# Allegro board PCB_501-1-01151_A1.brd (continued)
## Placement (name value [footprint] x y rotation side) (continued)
R204  10K  [0402]  93.85 53.34 90 top
R205  470E  [0402]  98.04 43.31 90 top
R206  470E  [0402]  96.9 43.31 90 top
R207  470E  [0402]  97.66 37.97 90 top
R208  10K  [0402]  94.49 60.32 90 top
R209  10K  [0402]  46.74 22.99 90 top
R210  10K  [0402]  49.02 22.99 90 top
R211  10K  [0402]  47.88 22.99 90 top
R212  10K  [0402]  43.31 22.99 90 top
R213  10K  [0402]  44.45 22.99 90 top
R214  10K  [0402]  51.31 22.99 90 top
R215  10K  [0402]  50.16 22.99 90 top
R216  10K  [0402]  45.59 22.99 90 top
R217  10K  [0402]  78.1 14.22 270 top
R218  10K  [0402]  77.34 10.41 90 top
R219  10K  [0402]  76.58 14.22 270 top
R220  10K  [0402]  75.82 10.41 90 top
R221  10K  [0402]  75.06 14.22 270 top
R222  10K  [0402]  74.29 10.41 90 top
R223  10K  [0402]  73.41 14.22 270 top
R224  10K  [0402]  72.64 10.41 90 top
R225  1K  [0402]  77.34 16 270 bottom
R226  1K  [0402]  78.49 16 270 bottom
R227  1K  [0402]  79.63 16 270 bottom
R228  1K  [0402]  69.34 10.41 270 top
R229  10K  [0402]  68.58 14.22 270 top
R230  10K  [0402]  69.34 8.76 270 top
R231  10K  [0402]  67.69 8.89 90 top
R232  1K  [0402]  80.77 16 270 bottom
R236  10K  [0402]  61.6 9.78 270 bottom
R238  10K  [0402]  62.48 11.3 270 bottom
R239  10K  [0402]  63.25 9.78 270 bottom
R240  10K  [0402]  68.71 14.22 270 bottom
R241  10K  [0402]  69.6 12.83 270 bottom
R242  10K  [0402]  70.41 14.25 270 bottom
R243  10K  [0402]  71.12 12.7 270 bottom
R244  10K  [0402]  71.88 14.22 270 bottom
R245  10K  [0402]  72.64 12.7 270 bottom
R246  10K  [0402]  73.41 14.22 270 bottom
R247  10K  [0402]  74.29 12.7 270 bottom
R248  10K  [0402]  75.06 14.22 270 bottom
R249  10K  [0402]  75.82 12.7 270 bottom
R250  10K  [0402]  76.58 14.22 270 bottom
R251  10K  [0402]  77.34 12.7 270 bottom
R252  10K  [0402]  78.1 14.22 270 bottom
R253  10K  [0402]  45.59 25.15 270 top
R254  10K  [0402]  50.16 25.15 270 top
R255  10K  [0402]  51.31 25.15 270 top
R256  10K  [0402]  44.45 25.15 270 top
R257  10K  [0402]  43.31 25.15 270 top
R258  10K  [0402]  47.88 25.15 270 top
R259  10K  [0402]  49.02 25.15 270 top
R260  10K  [0402]  46.74 25.15 270 top
R261  0E  [0402]  81.91 7.37 180 top
R262  100K  [0402]  83.69 5.97 180 top
R263  510K  [0402]  52.58 50.42 0 top
R264  0E  [0402]  2.79 49.02 0 top
R265  10K  [0402]  12.45 72.01 0 top
R266  10K  [0402]  12.45 69.47 0 top
R267  10K  [0402]  12.45 59.31 0 top
R387  10K  [0402]  33.91 40.51 180 bottom
R569  4.7K  [0402]  33.91 39.37 0 bottom
R571  2.2K  [0402]  50.16 11.68 90 bottom
R572  2.2K  [0402]  51.31 11.68 270 bottom
R574  2.2K  [0402]  52.07 29.46 90 bottom
R575  10K  [0402]  95.12 30.35 180 bottom
R576  10K  [0402]  95.12 31.5 180 bottom
R577  12K  [0402]  76.59 73.59 270 top
R578  10K  [0402]  93.6 80.39 180 top
R579  10K  [0402]  93.6 81.53 0 top
R580  10K  [0402]  18.29 68.2 90 top
R581  10K  [0402]  17.02 54.1 90 top
R763  200K  [0402]  37.97 64.13 90 bottom
R765  10K  [0402]  34.67 60.45 90 bottom
R766  1K  [0402]  42.67 63.5 90 bottom
R768  0E  [0402]  44.45 66.04 270 bottom
R769  0E  [0402]  52.07 60.71 180 top
R770  10K  [0402]  44.7 39.24 0 top
R771  0E  [0402]  91.69 86.87 90 top
R772  100K  [0402]  30.1 40.89 90 bottom
R773  49.9E  [0402]  51.69 37.59 90 bottom
R779  49.9E  [0402]  51.69 39.37 270 bottom
R780  10mE  [0603]  53.59 57.53 180 top
R781  1K  [0402]  22.48 55.24 90 top
R782  1K  [0402]  23.62 55.24 270 top
R783  2.2K  [0402]  53.59 11.68 270 bottom
R784  2.2K  [0402]  53.85 25.91 90 bottom
R785  2.2K  [0402]  48.9 17.27 90 top
R790  49.9E  [0402]  33.78 19.18 90 bottom
R791  49.9E  [0402]  33.78 17.27 90 bottom
R792  49.9E  [0402]  33.78 15.24 90 bottom
R793  49.9E  [0402]  33.78 13.34 90 bottom
R794  49.9E  [0402]  33.53 24.13 270 bottom
R795  49.9E  [0402]  33.53 26.03 270 bottom
R796  49.9E  [0402]  33.53 27.81 270 bottom
R797  49.9E  [0402]  33.53 29.72 270 bottom
R798  2.2K  [0402]  45.34 10.8 180 bottom
R799  2.2K  [0402]  45.85 30.99 180 bottom
R800  0E  [0402]  33.27 87.76 180 bottom
R801  0E  [0402]  33.27 89.03 180 bottom
R802  0E  [0402]  37.59 67.69 0 top
R803  0E  [0402]  58.17 58.29 90 top
R805  100K  [0402]  30.86 38.48 270 top
R806  100K  [0402]  29.84 85.6 180 bottom
R807  10K  [0402]  79.86 13.64 180 bottom
R808  10K  [0402]  79.88 12.45 0 bottom
R809  33E  [0402]  72.64 33.15 0 bottom
R810  0E  [0402]  36.2 17.02 0 top
R811  0E  [0402]  36.17 15.43 0 top
R812  0E  [0402]  35.92 25.43 0 top
R813  0E  [0402]  35.81 27.88 0 top
R814  10K  [0402]  36.2 39.37 0 bottom
R815  10K  [0402]  36.2 40.51 0 bottom
R816  10K  [0402]  63.75 62.74 0 top
R817  10K  [0402]  61.72 66.42 90 top
R818  10K  [0402]  61.98 70.49 180 top
R819  10K  [0402]  61.85 72.77 180 top
R820  10K  [0402]  68.33 62.74 270 top
R821  2.2M  [0402]  55.12 54.23 90 top
R822  22E  [0402]  68.07 21.72 0 top
R823  22E  [0402]  68.07 24 0 top
R824  22E  [0402]  68.07 25.15 0 top
R825  22E  [0402]  68.07 19.43 0 top
R826  22E  [0402]  68.07 20.57 0 top
R827  22E  [0402]  68.07 22.86 0 top
R828  22E  [0402]  68.07 26.29 0 top
R829  22E  [0402]  68.07 27.43 0 top
R830  22E  [0402]  68.07 17.14 0 top
R831  0E  [0402]  7.49 42.29 90 bottom
R832  10K  [0402]  47.37 43.56 0 bottom
R833  0E  [0402]  91.57 82.8 180 top
R834  0E  [0402]  11.3 49.02 0 top
R835  0E  [0402]  11.3 47.75 0 top
R836  100K  [0402]  31.24 37.97 180 bottom
R839  100K  [0402]  31.24 36.83 0 bottom
R840  100K  [0402]  31.24 39.12 0 bottom
R841  0E  [0402]  14.86 52.7 90 top
R842  0E  [0402]  93.98 68.58 0 top
R843  200K  [0402]  93.98 69.85 0 top
R844  2.2K  [0402]  39.37 11.3 90 bottom
R845  2.2K  [0402]  38.1 11.3 270 bottom
R846  2.2K  [0402]  40.13 32.89 270 bottom
R847  2.2K  [0402]  38.99 32.89 90 bottom
R848  10K  [0402]  12.45 74.55 180 top
R851  10K  [0402]  12.45 64.39 180 top
R852  10K  [0402]  12.45 61.85 180 top
R854  10K  [0402]  12.45 56.77 0 top
R855  10K  [0402]  12.45 52.96 0 top
R856  0E  [0402]  12.45 54.23 0 top
R857  0E  [0402]  12.45 51.69 0 top
R858  47K  [0402]  66.29 27.43 0 top
R859  0E  [0402]  53.34 65.91 270 top
R860  0E  [0402]  52.2 65.91 270 top
R861  0E  [0402]  41.66 11.3 270 bottom
R862  0E  [0402]  45.21 33.53 0 top
R863  2.2K  [0402]  40.51 11.3 90 bottom
R864  2.2K  [0402]  41.27 32.89 270 bottom
R865  0E  [0402]  33.27 90.17 180 bottom
R866  100K  [0402]  62.23 55.24 270 bottom
R867  100K  [0402]  11.68 46.23 0 top
R868  100K  [0402]  11.81 43.94 0 top
R869  100K  [0402]  23.75 46.1 270 top
R870  100K  [0402]  73.41 56.77 180 top
R871  100K  [0402]  65.28 53.98 270 bottom
R872  0E  [0402]  94.23 54.74 0 top
R873  0E  [0402]  94.87 62.1 0 top
R874  100K  [0402]  96.14 85.72 270 top
R875  0E  [0402]  17.02 68.2 270 top
R876  0E  [0402]  17.02 55.75 270 top
SW1  OS102011MS2QN1  [SW3_2_8P6X4P3_TH_ST]  15.49 96.27 0 top
SW2  B3U-3100PM-B  [SW3_1P7_3X2P5_SM_RA_A1]  98.75 69.72 270 top
SW3  B3U-3100PM-B  [SW3_1P7_3X2P5_SM_RA_A1]  98.75 75.69 270 top
SW4  B3U-3100PM-B  [SW3_1P7_3X2P5_SM_RA_A1]  98.75 53.09 270 top
SW5  B3U-3100PM-B  [SW3_1P7_3X2P5_SM_RA_A1]  98.75 59.31 270 top
SW6  TDA04H0SB1  [SW04_1P27_6P21X6P2]  71.37 20.19 0 bottom
SW7  TDA02H0SB1  [SW4_1P27_3P67X6P2]  92.58 37.21 0 bottom
SW8  B3U-3100PM-B  [SW3_1P7_3X2P5_SM_RA_A1]  98.75 81.66 270 top
TP1  SMD  [TP40_SMD]  29.08 81.15 0 top
TP3  SMD  [TP35_SMD]  69.72 33.02 180 bottom
TP4  SMD  [TP35_SMD]  76.45 29.46 180 bottom
TP5  SMD  [TP40_SMD]  50.04 20.19 0 top
TP6  SMD  [TP40_SMD]  47.12 20.57 0 top
TP7  SMD  [TP40_SMD]  17.91 52.58 0 top
TP8  SMD  [TP40_SMD]  50.42 68.96 90 top
TP9  SMD  [TP40_SMD]  49.91 46.1 90 top
TP10  SMD  [TP40_SMD]  46.1 44.2 0 top
TP11  SMD  [TP40_SMD]  32 54.1 90 top
TP12  SMD  [TP40_SMD]  38.1 43.18 0 top
TP13  SMD  [TP40_SMD]  34.67 89.15 90 top
TP30  SMD  [TP40_SMD_A1]  86.76 73.19 0 top
TP31  SMD  [TP40_SMD_A1]  41.78 5.84 0 top
TP32  SMD  [TP40_SMD_A1]  42.16 76.2 0 top
TP33  SMD  [TP40_SMD]  54.1 49.91 0 top
TP34  SMD  [TP40_SMD]  96.77 78.61 0 top
TP35  SMD  [TP40_SMD]  15.11 67.82 0 top
TP36  SMD  [TP40_SMD]  36.7 69.98 0 top
TP37  SMD  [TP40_SMD]  45.85 71.75 0 top
TP38  SMD  [TP40_SMD]  54.48 56.13 0 top
TP39  SMD  [TP40_SMD]  35.18 60.32 0 top
TP40  SMD  [TP40_SMD]  56.77 64.01 0 top
TP41  SMD  [TP40_SMD_A1]  88 47.84 180 bottom
TP42  SMD  [TP40_SMD_A1]  42.89 73.37 180 bottom
TP43  SMD  [TP40_SMD_A1]  47 4.53 180 bottom
TP44  SMD  [TP40_SMD]  47.88 50.16 0 top
TP45  SMD  [TP40_SMD]  45.72 46.86 0 top
TP46  SMD  [TP40_SMD]  39.62 50.55 0 top
TP47  SMD  [TP40_SMD]  45.85 67.69 0 top
TP48  SMD  [TP40_SMD]  40.39 38.23 0 top
TP49  SMD  [TP40_SMD]  60.2 32.13 180 bottom
TP50  SMD  [TP40_SMD]  68.07 44.2 180 bottom
TP51  SMD  [TP40_SMD]  58.8 29.97 180 bottom
TP52  SMD  [TP40_SMD]  55.24 53.98 180 bottom
TP53  SMD  [TP40_SMD]  64.01 49.02 180 bottom
TP54  SMD  [TP40_SMD]  49.78 49.02 180 bottom
TP55  SMD  [TP_3P8X2P03_SMD_A1]  95.1 64.73 0 top
TP56  SMD  [TP_3P8X2P03_SMD_A1]  28.36 96.37 90 top
TP57  SMD  [TP_3P8X2P03_SMD_A1]  94.72 13.3 0 top
TP58  SMD  [TP40_SMD]  42.93 35.18 0 top
TP59  SMD  [TP40_SMD]  39.24 35.31 0 top
TP60  SMD  [TP40_SMD]  44.96 41.15 0 top
U1  TPS6521815RSL  [VQFN48_0P4_6X6_EP_A1]  44.07 58.93 180 top
U2  SN74LV1T126DCK  [SC70-5L_0P65_2X1P25_B_A1]  55.75 60.71 270 top
U3  TPS22964C  [BGA6_0P5_0P942X1P442_A1]  29.84 40.26 0 top
U4  FPF1321UCX  [WLCSP6_0P5_0P96X1P46_A1]  91.19 23.11 90 top
U5  TPS22964C  [BGA6_0P5_0P942X1P442_A1]  32.13 83.44 180 top
U6  MCIMX6Y2CVM08AB  [BGA289_0P8_14X14_A1]  60.2 41.78 180 top
U7  MT41K256M16TW-107:P  [BGA96_0P8_8X14_A1]  81.41 40.01 0 top
U8  MTFC8GAKAJCN-4M  [BGA153_0P5_11P5X13_C_A1]  77.22 24.64 90 top
U9  MT25QU256ABA1EW7  [WPDFN8_1P27_6X5_EP_A1]  72.26 29.08 0 bottom
U10  DP83849IDVS  [QFP80_0P5_12X12]  45.47 20.7 180 bottom
U11  PUSB3F96  [DFN2510A-10L_0P5_2P5X1]  30.61 16.26 270 bottom
U12  PUSB3F96  [DFN2510A-10L_0P5_2P5X1]  29.97 27.94 90 bottom
U13  AT24C02C-MAHM  [UDFN8_0P5_3X2_EP_A_A1]  83.44 61.47 90 bottom
U14  USB2517I  [QFN64_0P5_9X9_EP_Y_A1]  70.74 69.34 270 top
U15  PUSB3F96  [DFN2510A-10L_0P5_2P5X1]  79.5 79.12 270 top
U16  PUSB3F96  [DFN2510A-10L_0P5_2P5X1]  60.96 79.25 90 top
U17  PUSB3F96  [DFN2510A-10L_0P5_2P5X1]  5.46 29.84 0 top
U18  TPS2054BD  [SOIC16_1P27_3P9X9P9_A1]  90.42 62.87 90 bottom
U19  MIC2026-1YM  [SOIC8_1P27_4X5]  54.61 72.39 180 bottom
U20  FT230XS  [SSOP16_0P635_5X4]  14.86 45.09 180 bottom
U21  ECMF02-2  [BGA5_0P4_0P83X1P23_A1]  8.51 40.51 180 top
U22  INA3221AIRGV  [QFN16_0P65_4X4_EP_I_A1]  30.86 45.97 270 bottom
U23  INA3221AIRGV  [QFN16_0P65_4X4_EP_I_A1]  34.92 69.6 0 bottom
U24  TSC2046IPW  [TSSOP16_0P65_4P4X5_F_A1]  63.63 15.88 0 bottom
U26  TPS3422EGDRY  [SON6_0P5_1X1P45_A1]  91.69 80.9 270 top
U27  SN74LV1T126DCK  [SC70-5L_0P65_2X1P25_B_A1]  93.73 87.5 180 top
X1  24MHz  [XTAL4_1P55_3P2X2P5]  81.74 71.91 270 top
X2  32.768KHz  [XTAL2_2P5_3P2X1P5]  62.54 52 90 bottom
X3  24MHz  [XTAL4_1P6_3P2X2P5_A_A1]  52.2 53.85 0 top
Y1  50MHz  [OSC4_2P2_5P2X3P4]  55.74 17.18 90 bottom

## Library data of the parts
BH1 = BATT_HOLDER_3P_B
C1 C2 C4-C24 C26-C143 C149-C177 C180-C201 C204 C205 C572-C577 C583-C589 C591-C594 C596-C607 = CAP_NP
C3 C590 = CAP_POL
D1 = DIODE_ZEN
D2 D6 D9 D12 D26-D29 = DIODE_SCH
D4 D5 D7 D8 D10 D11 = DIODE_LED
D15 = DIODE_LED_A
DA1-DA6 = DIODE_NETX2_LED-GR_4P
DA8 = DIODE_NETX2_LED-BO_4P
F1 = FUSE
FB1 FB3-FB20 = FER_BEAD
FD1-FD6 = MECH_FID_G
FD7-FD12 = MECH_FID_L
FL1-FL6 = FIL_COM-MODE_4P_C_POL
H1 = HDR_2X5_10P
H4 H5 = HDR_2X10_20P
J1 = CONN_PWRJACK_4P_A_A1
J2 = CONN_MICROSD-8_12P_B
J3 = CONN_RJ45-17X2_39P_A_A1
J4 J5 = CONN_USBA-4X2_12P
J6 = CONN_USBA-4X1_8P
J7 = CONN_USB-5X1_9P
J8 = CONN_USB-5X1_11P
J9 = CONN_FPC-40_42P
L1-L4 = IND_CORE_A
L5-L7 = IND_CORE_B
MH1-MH8 = MECH_MH_PL
P1-P15 = PROT_ZENX2_NET_2P_A
Q1 = TRANS_PMOSX1_8P
Q2 = TRANS_PNP
Q3 = TRANS_NMOS-ENX1_3P
Q4-Q6 = TRANS_PMOS-ENX1_3P_C
Q17 Q41 = TRANS_NPN
R1 R3-R28 R31-R37 R58 R60 R62-R90 R94-R110 R112-R232 R236 R238-R267 R387 R569 R571 R572 R574-R581 R763 R765 R766 R768-R773 R779-R785 R790-R803 R805-R836 R839-R848 R851 R852 R854-R876 = RES
SW1 = SWITCH_SPDT_5P
SW2-SW5 SW8 = SWITCH_PUSH-2_3P_A
SW6 = SWITCH_DIPX4_8P_B
SW7 = SWITCH_DIPX2_4P_B
TP1 TP3-TP13 TP30-TP60 = TEST_POINT_SMD
U1 = IC_TPS65218D0_QFN-48P_EP_CST_A2
U2 U27 = IC_GATE_BUFX1_5P_H_A1
U3 U5 = IC_LOAD_SWITCH_6P_F_A1
U4 = IC_LOAD_SWITCH_6P_N_A1
U6 = IC_IMX6ULL_BGA-289P_CST_A1
U7 = IC_DDR3-SDRAMX16_BGA-96P_D
U8 = IC_NAND_FLASHx8_BGA-153P_J_A1
U9 = IC_NORFLASH-SPI_8P_EP_G_A1
U10 = IC_DP83849ID_TQFP-80P
U11 U12 U15-U17 = IC_PUSB3F96_DFN-10P
U13 = IC_EEPROM-I2C_8P_EP_B_A1
U14 = IC_USB2517_QFN-64P_EP_CUST_A1
U18 = IC_PWRSWITCHx4_16P_C_A1
U19 = IC_PWRSWITCH_8P_D_A1
U20 = IC_FT230X_SSOP-16P
U21 = IC_FIL_COM-MODE_WLCSP-5P
U22 U23 = IC_INA3221_VQFN-16P_EP_A1
U24 = IC_TSC2046_TSSOP-16P_A1
U26 = IC_TPS3422_USON-6P_A1
X1 = CRYSTAL_4P_D
X2 = CRYSTAL
X3 = CRYSTAL_4P
Y1 = OSC_4P_A

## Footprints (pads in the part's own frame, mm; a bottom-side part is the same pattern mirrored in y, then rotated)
0201
  rect 0.508x0.508 smd: 1(-0.354,0) 2(0.354,0)
0402
  rect 0.533x0.533 smd: 1(-0.4,0) 2(0.4,0)
0603
  rect 0.965x1.016 smd: 1(-0.8,0) 2(0.8,0)
0805
  rect 1.143x1.448 smd: 1(-0.9,0) 2(0.9,0)
0805_B_A1
  rect 0.711x1.321 smd: 1(-0.95,0) 2(0.95,0)
BAT3_21P97_21P08X15P24_A1
  rect 2.794x5.08 smd: 1(-10.985,0) 3(10.985,0)
  round 17.78 smd: 2(0,0)
BGA5_0P4_0P83X1P23_A1
  round 0.229 smd: A1(-0.2,0.4) A2(0.2,0.4) B1(-0.2,0) B2(0.2,0) C2(0.2,-0.4)
BGA6_0P5_0P942X1P442_A1
  round 0.229 smd: A1(-0.25,0.5) A2(0.25,0.5) B1(-0.25,0) B2(0.25,0) C1(-0.25,-0.5) C2(0.25,-0.5)
BGA96_0P8_8X14_A1
  round 0.356 smd: A1(-3.2,6) A2(-2.4,6) A3(-1.6,6) A7(1.6,6) A8(2.4,6) A9(3.2,6) B1(-3.2,5.2) B2(-2.4,5.2) B3(-1.6,5.2) B7(1.6,5.2) B8(2.4,5.2) B9(3.2,5.2) C1(-3.2,4.4) C2(-2.4,4.4) C3(-1.6,4.4) C7(1.6,4.4) C8(2.4,4.4) C9(3.2,4.4) D1(-3.2,3.6) D2(-2.4,3.6) D3(-1.6,3.6) D7(1.6,3.6) D8(2.4,3.6) D9(3.2,3.6) E1(-3.2,2.8) E2(-2.4,2.8) E3(-1.6,2.8) E7(1.6,2.8) E8(2.4,2.8) E9(3.2,2.8) F1(-3.2,2) F2(-2.4,2) F3(-1.6,2) F7(1.6,2) F8(2.4,2) F9(3.2,2) G1(-3.2,1.2) G2(-2.4,1.2) G3(-1.6,1.2) G7(1.6,1.2) G8(2.4,1.2) G9(3.2,1.2) H1(-3.2,0.4) H2(-2.4,0.4) H3(-1.6,0.4) H7(1.6,0.4) H8(2.4,0.4) H9(3.2,0.4) J1(-3.2,-0.4) J2(-2.4,-0.4) J3(-1.6,-0.4) J7(1.6,-0.4) J8(2.4,-0.4) J9(3.2,-0.4) K1(-3.2,-1.2) K2(-2.4,-1.2) K3(-1.6,-1.2) K7(1.6,-1.2) K8(2.4,-1.2) K9(3.2,-1.2) L1(-3.2,-2) L2(-2.4,-2) L3(-1.6,-2) L7(1.6,-2) L8(2.4,-2) L9(3.2,-2) M1(-3.2,-2.8) M2(-2.4,-2.8) M3(-1.6,-2.8) M7(1.6,-2.8) M8(2.4,-2.8) M9(3.2,-2.8) N1(-3.2,-3.6) N2(-2.4,-3.6) N3(-1.6,-3.6) N7(1.6,-3.6) N8(2.4,-3.6) N9(3.2,-3.6) P1(-3.2,-4.4) P2(-2.4,-4.4) P3(-1.6,-4.4) P7(1.6,-4.4) P8(2.4,-4.4) P9(3.2,-4.4) R1(-3.2,-5.2) R2(-2.4,-5.2) R3(-1.6,-5.2) R7(1.6,-5.2) R8(2.4,-5.2) R9(3.2,-5.2) T1(-3.2,-6) T2(-2.4,-6) T3(-1.6,-6) T7(1.6,-6) T8(2.4,-6) T9(3.2,-6)
BGA153_0P5_11P5X13_C_A1
  round 0.254 smd: A1(-3.25,3.25) A2(-2.75,3.25) A3(-2.25,3.25) A4(-1.75,3.25) A5(-1.25,3.25) A6(-0.75,3.25) A7(-0.25,3.25) A8(0.25,3.25) A9(0.75,3.25) A10(1.25,3.25) A11(1.75,3.25) A12(2.25,3.25) A13(2.75,3.25) A14(3.25,3.25) B1(-3.25,2.75) B2(-2.75,2.75) B3(-2.25,2.75) B4(-1.75,2.75) B5(-1.25,2.75) B6(-0.75,2.75) B7(-0.25,2.75) B8(0.25,2.75) B9(0.75,2.75) B10(1.25,2.75) B11(1.75,2.75) B12(2.25,2.75) B13(2.75,2.75) B14(3.25,2.75) C1(-3.25,2.25) C2(-2.75,2.25) C3(-2.25,2.25) C4(-1.75,2.25) C5(-1.25,2.25) C6(-0.75,2.25) C7(-0.25,2.25) C8(0.25,2.25) C9(0.75,2.25) C10(1.25,2.25) C11(1.75,2.25) C12(2.25,2.25) C13(2.75,2.25) C14(3.25,2.25) D1(-3.25,1.75) D2(-2.75,1.75) D3(-2.25,1.75) D4(-1.75,1.75) D12(2.25,1.75) D13(2.75,1.75) D14(3.25,1.75) E1(-3.25,1.25) E2(-2.75,1.25) E3(-2.25,1.25) E5(-1.25,1.25) E6(-0.75,1.25) E7(-0.25,1.25) E8(0.25,1.25) E9(0.75,1.25) E10(1.25,1.25) E12(2.25,1.25) E13(2.75,1.25) E14(3.25,1.25) F1(-3.25,0.75) F2(-2.75,0.75) F3(-2.25,0.75) F5(-1.25,0.75) F10(1.25,0.75) F12(2.25,0.75) F13(2.75,0.75) F14(3.25,0.75) G1(-3.25,0.25) G2(-2.75,0.25) G3(-2.25,0.25) G5(-1.25,0.25) G10(1.25,0.25) G12(2.25,0.25) G13(2.75,0.25) G14(3.25,0.25) H1(-3.25,-0.25) H2(-2.75,-0.25) H3(-2.25,-0.25) H5(-1.25,-0.25) H10(1.25,-0.25) H12(2.25,-0.25) H13(2.75,-0.25) H14(3.25,-0.25) J1(-3.25,-0.75) J2(-2.75,-0.75) J3(-2.25,-0.75) J5(-1.25,-0.75) J10(1.25,-0.75) J12(2.25,-0.75) J13(2.75,-0.75) J14(3.25,-0.75) K1(-3.25,-1.25) K2(-2.75,-1.25) K3(-2.25,-1.25) K5(-1.25,-1.25) K6(-0.75,-1.25) K7(-0.25,-1.25) K8(0.25,-1.25) K9(0.75,-1.25) K10(1.25,-1.25) K12(2.25,-1.25) K13(2.75,-1.25) K14(3.25,-1.25) L1(-3.25,-1.75) L2(-2.75,-1.75) L3(-2.25,-1.75) L12(2.25,-1.75) L13(2.75,-1.75) L14(3.25,-1.75) M1(-3.25,-2.25) M2(-2.75,-2.25) M3(-2.25,-2.25) M4(-1.75,-2.25) M5(-1.25,-2.25) M6(-0.75,-2.25) M7(-0.25,-2.25) M8(0.25,-2.25) M9(0.75,-2.25) M10(1.25,-2.25) M11(1.75,-2.25) M12(2.25,-2.25) M13(2.75,-2.25) M14(3.25,-2.25) N1(-3.25,-2.75) N2(-2.75,-2.75) N3(-2.25,-2.75) N4(-1.75,-2.75) N5(-1.25,-2.75) N6(-0.75,-2.75) N7(-0.25,-2.75) N8(0.25,-2.75) N9(0.75,-2.75) N10(1.25,-2.75) N11(1.75,-2.75) N12(2.25,-2.75) N13(2.75,-2.75) N14(3.25,-2.75) P1(-3.25,-3.25) P2(-2.75,-3.25) P3(-2.25,-3.25) P4(-1.75,-3.25) P5(-1.25,-3.25) P6(-0.75,-3.25) P7(-0.25,-3.25) P8(0.25,-3.25) P9(0.75,-3.25) P10(1.25,-3.25) P11(1.75,-3.25) P12(2.25,-3.25) P13(2.75,-3.25) P14(3.25,-3.25)
BGA289_0P8_14X14_A1
  round 0.305 smd: A1(-6.4,6.4) A2(-5.6,6.4) A3(-4.8,6.4) A4(-4,6.4) A5(-3.2,6.4) A6(-2.4,6.4) A7(-1.6,6.4) A8(-0.8,6.4) A9(0,6.4) A10(0.8,6.4) A11(1.6,6.4) A12(2.4,6.4) A13(3.2,6.4) A14(4,6.4) A15(4.8,6.4) A16(5.6,6.4) A17(6.4,6.4) B1(-6.4,5.6) B2(-5.6,5.6) B3(-4.8,5.6) B4(-4,5.6) B5(-3.2,5.6) B6(-2.4,5.6) B7(-1.6,5.6) B8(-0.8,5.6) B9(0,5.6) B10(0.8,5.6) B11(1.6,5.6) B12(2.4,5.6) B13(3.2,5.6) B14(4,5.6) B15(4.8,5.6) B16(5.6,5.6) B17(6.4,5.6) C1(-6.4,4.8) C2(-5.6,4.8) C3(-4.8,4.8) C4(-4,4.8) C5(-3.2,4.8) C6(-2.4,4.8) C7(-1.6,4.8) C8(-0.8,4.8) C9(0,4.8) C10(0.8,4.8) C11(1.6,4.8) C12(2.4,4.8) C13(3.2,4.8) C14(4,4.8) C15(4.8,4.8) C16(5.6,4.8) C17(6.4,4.8) D1(-6.4,4) D2(-5.6,4) D3(-4.8,4) D4(-4,4) D5(-3.2,4) D6(-2.4,4) D7(-1.6,4) D8(-0.8,4) D9(0,4) D10(0.8,4) D11(1.6,4) D12(2.4,4) D13(3.2,4) D14(4,4) D15(4.8,4) D16(5.6,4) D17(6.4,4) E1(-6.4,3.2) E2(-5.6,3.2) E3(-4.8,3.2) E4(-4,3.2) E5(-3.2,3.2) E6(-2.4,3.2) E7(-1.6,3.2) E8(-0.8,3.2) E9(0,3.2) E10(0.8,3.2) E11(1.6,3.2) E12(2.4,3.2) E13(3.2,3.2) E14(4,3.2) E15(4.8,3.2) E16(5.6,3.2) E17(6.4,3.2) F1(-6.4,2.4) F2(-5.6,2.4) F3(-4.8,2.4) F4(-4,2.4) F5(-3.2,2.4) F6(-2.4,2.4) F7(-1.6,2.4) F8(-0.8,2.4) F9(0,2.4) F10(0.8,2.4) F11(1.6,2.4) F12(2.4,2.4) F13(3.2,2.4) F14(4,2.4) F15(4.8,2.4) F16(5.6,2.4) F17(6.4,2.4) G1(-6.4,1.6) G2(-5.6,1.6) G3(-4.8,1.6) G4(-4,1.6) G5(-3.2,1.6) G6(-2.4,1.6) G7(-1.6,1.6) G8(-0.8,1.6) G9(0,1.6) G10(0.8,1.6) G11(1.6,1.6) G12(2.4,1.6) G13(3.2,1.6) G14(4,1.6) G15(4.8,1.6) G16(5.6,1.6) G17(6.4,1.6) H1(-6.4,0.8) H2(-5.6,0.8) H3(-4.8,0.8) H4(-4,0.8) H5(-3.2,0.8) H6(-2.4,0.8) H7(-1.6,0.8) H8(-0.8,0.8) H9(0,0.8) H10(0.8,0.8) H11(1.6,0.8) H12(2.4,0.8) H13(3.2,0.8) H14(4,0.8) H15(4.8,0.8) H16(5.6,0.8) H17(6.4,0.8) J1(-6.4,0) J2(-5.6,0) J3(-4.8,0) J4(-4,0) J5(-3.2,0) J6(-2.4,0) J7(-1.6,0) J8(-0.8,0) J9(0,0) J10(0.8,0) J11(1.6,0) J12(2.4,0) J13(3.2,0) J14(4,0) J15(4.8,0) J16(5.6,0) J17(6.4,0) K1(-6.4,-0.8) K2(-5.6,-0.8) K3(-4.8,-0.8) K4(-4,-0.8) K5(-3.2,-0.8) K6(-2.4,-0.8) K7(-1.6,-0.8) K8(-0.8,-0.8) K9(0,-0.8) K10(0.8,-0.8) K11(1.6,-0.8) K12(2.4,-0.8) K13(3.2,-0.8) K14(4,-0.8) K15(4.8,-0.8) K16(5.6,-0.8) K17(6.4,-0.8) L1(-6.4,-1.6) L2(-5.6,-1.6) L3(-4.8,-1.6) L4(-4,-1.6) L5(-3.2,-1.6) L6(-2.4,-1.6) L7(-1.6,-1.6) L8(-0.8,-1.6) L9(0,-1.6) L10(0.8,-1.6) L11(1.6,-1.6) L12(2.4,-1.6) L13(3.2,-1.6) L14(4,-1.6) L15(4.8,-1.6) L16(5.6,-1.6) L17(6.4,-1.6) M1(-6.4,-2.4) M2(-5.6,-2.4) M3(-4.8,-2.4) M4(-4,-2.4) M5(-3.2,-2.4) M6(-2.4,-2.4) M7(-1.6,-2.4) M8(-0.8,-2.4) M9(0,-2.4) M10(0.8,-2.4) M11(1.6,-2.4) M12(2.4,-2.4) M13(3.2,-2.4) M14(4,-2.4) M15(4.8,-2.4) M16(5.6,-2.4) M17(6.4,-2.4) N1(-6.4,-3.2) N2(-5.6,-3.2) N3(-4.8,-3.2) N4(-4,-3.2) N5(-3.2,-3.2) N6(-2.4,-3.2) N7(-1.6,-3.2) N8(-0.8,-3.2) N9(0,-3.2) N10(0.8,-3.2) N11(1.6,-3.2) N12(2.4,-3.2) N13(3.2,-3.2) N14(4,-3.2) N15(4.8,-3.2) N16(5.6,-3.2) N17(6.4,-3.2) P1(-6.4,-4) P2(-5.6,-4) P3(-4.8,-4) P4(-4,-4) P5(-3.2,-4) P6(-2.4,-4) P7(-1.6,-4) P8(-0.8,-4) P9(0,-4) P10(0.8,-4) P11(1.6,-4) P12(2.4,-4) P13(3.2,-4) P14(4,-4) P15(4.8,-4) P16(5.6,-4) P17(6.4,-4) R1(-6.4,-4.8) R2(-5.6,-4.8) R3(-4.8,-4.8) R4(-4,-4.8) R5(-3.2,-4.8) R6(-2.4,-4.8) R7(-1.6,-4.8) R8(-0.8,-4.8) R9(0,-4.8) R10(0.8,-4.8) R11(1.6,-4.8) R12(2.4,-4.8) R13(3.2,-4.8) R14(4,-4.8) R15(4.8,-4.8) R16(5.6,-4.8) R17(6.4,-4.8) T1(-6.4,-5.6) T2(-5.6,-5.6) T3(-4.8,-5.6) T4(-4,-5.6) T5(-3.2,-5.6) T6(-2.4,-5.6) T7(-1.6,-5.6) T8(-0.8,-5.6) T9(0,-5.6) T10(0.8,-5.6) T11(1.6,-5.6) T12(2.4,-5.6) T13(3.2,-5.6) T14(4,-5.6) T15(4.8,-5.6) T16(5.6,-5.6) T17(6.4,-5.6) U1(-6.4,-6.4) U2(-5.6,-6.4) U3(-4.8,-6.4) U4(-4,-6.4) U5(-3.2,-6.4) U6(-2.4,-6.4) U7(-1.6,-6.4) U8(-0.8,-6.4) U9(0,-6.4) U10(0.8,-6.4) U11(1.6,-6.4) U12(2.4,-6.4) U13(3.2,-6.4) U14(4,-6.4) U15(4.8,-6.4) U16(5.6,-6.4) U17(6.4,-6.4)
CM_CHK4_0P8_2X1P2
  rect 0.813x0.508 smd: 1(-1.05,-0.4) 2(1.05,-0.4) 3(1.05,0.4) 4(-1.05,0.4)
CON_BERG_2X10M_1P27_SM_ST_A_A1
  rect 0.737x2.413 smd: 1(-5.715,1.95) 2(-5.715,-1.95) 3(-4.445,1.95) 4(-4.445,-1.95) 5(-3.175,1.95) 6(-3.175,-1.95) 7(-1.905,1.95) 8(-1.905,-1.95) 9(-0.635,1.95) 10(-0.635,-1.95) 11(0.635,1.95) 12(0.635,-1.95) 13(1.905,1.95) 14(1.905,-1.95) 15(3.175,1.95) 16(3.175,-1.95) 17(4.445,1.95) 18(4.445,-1.95) 19(5.715,1.95) 20(5.715,-1.95)
CON_FPC_1X40F_0P5_SM_RA_N_A1
  rect 0.305x1.194 smd: 1(-9.75,0) 2(-9.25,0) 3(-8.75,0) 4(-8.25,0) 5(-7.75,0) 6(-7.25,0) 7(-6.75,0) 8(-6.25,0) 9(-5.75,0) 10(-5.25,0) 11(-4.75,0) 12(-4.25,0) 13(-3.75,0) 14(-3.25,0) 15(-2.75,0) 16(-2.25,0) 17(-1.75,0) 18(-1.25,0) 19(-0.75,0) 20(-0.25,0) 21(0.25,0) 22(0.75,0) 23(1.25,0) 24(1.75,0) 25(2.25,0) 26(2.75,0) 27(3.25,0) 28(3.75,0) 29(4.25,0) 30(4.75,0) 31(5.25,0) 32(5.75,0) 33(6.25,0) 34(6.75,0) 35(7.25,0) 36(7.75,0) 37(8.25,0) 38(8.75,0) 39(9.25,0) 40(9.75,0)
  custom 0.6x0.6 smd: M1(-11.85,-2.7) M2(11.85,-2.7)
CON_HDR_2X5M_2P54_SM_ST
  rect 1.27x3.683 smd: 1(-5.08,-2.475) 2(-5.08,2.475) 3(-2.54,-2.475) 4(-2.54,2.475) 5(0,-2.475) 6(0,2.475) 7(2.54,-2.475) 8(2.54,2.475) 9(5.08,-2.475) 10(5.08,2.475)
CON_HDR_2X10M_2P54_SM_CUST_A1
  rect 1.27x3.683 smd: 1(-11.43,-2.22) 2(-11.43,2.22) 3(-8.89,-2.22) 4(-8.89,2.22) 5(-6.35,-2.22) 6(-6.35,2.22) 7(-3.81,-2.22) 8(-3.81,2.22) 9(-1.27,-2.22) 10(-1.27,2.22) 11(1.27,-2.22) 12(1.27,2.22) 13(3.81,-2.22) 14(3.81,2.22) 15(6.35,-2.22) 16(6.35,2.22) 17(8.89,-2.22) 18(8.89,2.22) 19(11.43,-2.22) 20(11.43,2.22)
CON_PWR-JACK_2M_6_TH_RA_A_A1
  round 0.991 hole 1.6 unplated: (0,9)
  rect 5.41x2.007 hole 2.997x0.991: 1(0,0)
  rect 4.14x2.007 hole 2.311x0.991: 2(0,6)
  rect 2.007x4.496 hole 0.991x2.489: S1(-4.5,7) S2(4.5,7)
CON_RJ45_2X1_2P01_TH_RA_A1
  round 0.991 hole 3.302 unplated: (-0.492,-5.26) (12.618,-5.26)
  rect 1.499x1.499 hole 0.889: 1(0.033,0)
  round 1.499 hole 0.889: 2(2.043,0) 3(4.053,0) 4(6.063,0) 5(8.073,0) 6(10.083,0) 7(12.093,0) 8(1.023,2.54) 9(3.033,2.54) 10(5.043,2.54) 11(7.053,2.54) 12(9.063,2.54) 13(11.073,2.54) 14(0.033,10.41) 15(2.043,10.41) 16(4.053,10.41) 17(6.063,10.41) 18(8.073,10.41) 19(10.083,10.41) 20(12.093,10.41) 21(1.023,12.95) 22(3.033,12.95) 23(5.043,12.95) 24(7.053,12.95) 25(9.063,12.95) 26(11.073,12.95)
  round 1.676 hole 1.016: 27(0.118,-8.1) 28(2.153,-8.1) 29(9.973,-8.1) 30(12.008,-8.1) 31(0.603,16.76) 32(3.143,16.76) 33(8.983,16.76) 34(11.523,16.76)
  round 2.565 hole 1.575: S1(-2.332,6.53) S2(14.458,6.53) S3(14.458,-9.83) S4(-2.332,-9.83)
CON_USB-A_1X1F_2_TH_RA_D_A1
  rect 1.549x1.549 hole 0.914: 1(0,0)
  round 1.549 hole 0.914: 2(0,2) 3(0,4) 4(0,6)
  round 2.261 hole 1.346: S1(-2.72,-0.73) S2(2.72,-0.73) S3(-2.72,6.27) S4(2.72,6.27)
CON_USB-A_2X1F_2_TH_RA_A1
  rect 1.549x1.549 hole 0.914: 1(0,0)
  round 1.549 hole 0.914: 2(2.5,0) 3(4.5,0) 4(7,0) 5(0,-2.62) 6(2.5,-2.62) 7(4.5,-2.62) 8(7,-2.62)
  round 3.81 hole 2.311: S1(10.07,0.35) S2(-3.07,0.35) S3(-3.07,-5.33) S4(10.07,-5.33)
CON_USB_1X1-5F_0P65_SM_RA_D_A1
  rect 0.406x1.346 smd: 1(-1.3,0) 2(-0.65,0) 3(0,0) 4(0.65,0) 5(1.3,0)
  rect 1.6x1.397 smd: S1(-3.2,-0.225) S2(3.2,-0.225)
  oval 0.914x1.6 hole 0.508x1.194: S3(3.3,-2.675) S4(-3.3,-2.675)
  rect 1.905x1.905 smd: S5(-1.2,-2.675) S6(1.2,-2.675)
CON_USB_5F_0P65_SM_RA_A2
  rect 0.406x1.397 smd: 1(-1.3,0) 2(-0.65,0) 3(0,0) 4(0.65,0) 5(1.3,0)
  rect 2.311x1.905 smd: S1(-3.75,-2.85) S2(3.75,-2.85)
  rect 1.803x1.905 smd: S3(-1.15,-2.85) S4(1.15,-2.85)
CON_USD_1X1F_12L_1P1_SM_RA
  rect 0.813x1.499 smd: 1(-1.94,3.1) 2(-0.84,2.7) 3(0.26,3.1) 4(1.36,3.3) 5(2.46,3.1) 6(3.56,3.3) 7(4.66,3.1) 8(5.76,3.1)
  rect 1.803x1.397 smd: CD1(-0.75,-7.2) CD2(4.95,-7.2)
  rect 1.397x1.905 smd: COM1(-6.6,6.95) COM2(6.55,5.95)
DFN2510A-10L_0P5_2P5X1
  rect 0.254x0.66 smd: 1(-1,-0.425)
  rect 0.254x0.61 smd: 2(-0.5,-0.45) 3(0,-0.45) 4(0.5,-0.45) 5(1,-0.45) 6(1,0.45) 7(0.5,0.45) 8(0,0.45) 9(-0.5,0.45) 10(-1,0.45)
DIO-0201
  rect 0.305x0.305 smd: 1(-0.215,0) 2(0.215,0)
DIO-0402
  rect 0.508x0.711 smd: 1(-0.375,0) 2(0.375,0)
DIO_SOD-523_A1
  rect 0.483x0.406 smd: 1(-0.66,0) 2(0.66,0)
FUSE_1210_A1
  rect 1.092x2.642 smd: 1(-1.55,0) 2(1.55,0)
GFD40_120
  round 1.016 smd: 1(0,0)
IND-0805_1P45
  rect 1.168x1.575 smd: 1(-0.925,0) 2(0.925,0)
IND-2520_1_A1
  rect 0.813x2.007 smd: 1(-1,0) 2(1,0)
IND_0806_B_A1
  rect 0.559x1.6 smd: 1(-0.725,0) 2(0.725,0)
LED2_0P9_1X0P6
  rect 0.508x0.61 smd: 1(-0.45,0) 2(0.45,0)
LED4_0P7_1P6X0P8
  rect 0.711x0.406 smd: 1(-0.65,0.35) 2(-0.65,-0.35) 3(0.65,0.35) 4(0.65,-0.35)
LED4_0P85_1P5X1P6
  rect 0.66x0.864 smd: 1(-0.425,-0.725) 2(0.425,-0.725) 3(-0.425,0.725) 4(0.425,0.725)
LED-0603
  rect 1.016x0.914 smd: 1(-0.85,0) 2(0.85,0)
LED-0603_C_A1
  rect 0.787x0.787 smd: 1(-0.75,0) 2(0.75,0)
LFD40_80
  round 1.016 smd: 1(0,0)
MH165D87T_A1
  round 4.191 hole 2.21: 1(0,0)
MH236D126T_A1
  round 5.994 hole 3.2: 1(0,0)
MOSFET_0402-3L_A1
  rect 0.152x0.254 smd: 1(-0.175,-0.325) 2(0.175,-0.325)
  rect 0.508x0.254 smd: 3(0,0.325)
OSC4_2P2_5P2X3P4
  rect 1.702x1.499 smd: 1(-1.27,-1.1) 2(1.27,-1.1) 3(1.27,1.1) 4(-1.27,1.1)
QFN16_0P65_4X4_EP_I_A1
  rect 0.991x0.356 smd: 1(-1.9,0.975) 2(-1.9,0.325) 3(-1.9,-0.325) 4(-1.9,-0.975) 9(1.9,-0.975) 10(1.9,-0.325) 11(1.9,0.325) 12(1.9,0.975)
  rect 0.356x0.991 smd: 5(-0.975,-1.9) 6(-0.325,-1.9) 7(0.325,-1.9) 8(0.975,-1.9) 13(0.975,1.9) 14(0.325,1.9) 15(-0.325,1.9) 16(-0.975,1.9)
  rect 2.108x2.108 smd: 17(0,0)
QFN64_0P5_9X9_EP_Y_A1
  rect 0.686x0.279 smd: 1(-4.37,3.75) 2(-4.37,3.25) 3(-4.37,2.75) 4(-4.37,2.25) 5(-4.37,1.75) 6(-4.37,1.25) 7(-4.37,0.75) 8(-4.37,0.25) 9(-4.37,-0.25) 10(-4.37,-0.75) 11(-4.37,-1.25) 12(-4.37,-1.75) 13(-4.37,-2.25) 14(-4.37,-2.75) 15(-4.37,-3.25) 16(-4.37,-3.75) 33(4.37,-3.75) 34(4.37,-3.25) 35(4.37,-2.75) 36(4.37,-2.25) 37(4.37,-1.75) 38(4.37,-1.25) 39(4.37,-0.75) 40(4.37,-0.25) 41(4.37,0.25) 42(4.37,0.75) 43(4.37,1.25) 44(4.37,1.75) 45(4.37,2.25) 46(4.37,2.75) 47(4.37,3.25) 48(4.37,3.75)
  rect 0.279x0.686 smd: 17(-3.75,-4.37) 18(-3.25,-4.37) 19(-2.75,-4.37) 20(-2.25,-4.37) 21(-1.75,-4.37) 22(-1.25,-4.37) 23(-0.75,-4.37) 24(-0.25,-4.37) 25(0.25,-4.37) 26(0.75,-4.37) 27(1.25,-4.37) 28(1.75,-4.37) 29(2.25,-4.37) 30(2.75,-4.37) 31(3.25,-4.37) 32(3.75,-4.37) 49(3.75,4.37) 50(3.25,4.37) 51(2.75,4.37) 52(2.25,4.37) 53(1.75,4.37) 54(1.25,4.37) 55(0.75,4.37) 56(0.25,4.37) 57(-0.25,4.37) 58(-0.75,4.37) 59(-1.25,4.37) 60(-1.75,4.37) 61(-2.25,4.37) 62(-2.75,4.37) 63(-3.25,4.37) 64(-3.75,4.37)
  rect 4.699x4.699 smd: 65(0,0)
QFP80_0P5_12X12
  rect 0.279x1.245 smd: 1(-4.75,-6.625) 2(-4.25,-6.625) 3(-3.75,-6.625) 4(-3.25,-6.625) 5(-2.75,-6.625) 6(-2.25,-6.625) 7(-1.75,-6.625) 8(-1.25,-6.625) 9(-0.75,-6.625) 10(-0.25,-6.625) 11(0.25,-6.625) 12(0.75,-6.625) 13(1.25,-6.625) 14(1.75,-6.625) 15(2.25,-6.625) 16(2.75,-6.625) 17(3.25,-6.625) 18(3.75,-6.625) 19(4.25,-6.625) 20(4.75,-6.625) 41(4.75,6.625) 42(4.25,6.625) 43(3.75,6.625) 44(3.25,6.625) 45(2.75,6.625) 46(2.25,6.625) 47(1.75,6.625) 48(1.25,6.625) 49(0.75,6.625) 50(0.25,6.625) 51(-0.25,6.625) 52(-0.75,6.625) 53(-1.25,6.625) 54(-1.75,6.625) 55(-2.25,6.625) 56(-2.75,6.625) 57(-3.25,6.625) 58(-3.75,6.625) 59(-4.25,6.625) 60(-4.75,6.625)
  rect 1.245x0.279 smd: 21(6.625,-4.75) 22(6.625,-4.25) 23(6.625,-3.75) 24(6.625,-3.25) 25(6.625,-2.75) 26(6.625,-2.25) 27(6.625,-1.75) 28(6.625,-1.25) 29(6.625,-0.75) 30(6.625,-0.25) 31(6.625,0.25) 32(6.625,0.75) 33(6.625,1.25) 34(6.625,1.75) 35(6.625,2.25) 36(6.625,2.75) 37(6.625,3.25) 38(6.625,3.75) 39(6.625,4.25) 40(6.625,4.75) 61(-6.625,4.75) 62(-6.625,4.25) 63(-6.625,3.75) 64(-6.625,3.25) 65(-6.625,2.75) 66(-6.625,2.25) 67(-6.625,1.75) 68(-6.625,1.25) 69(-6.625,0.75) 70(-6.625,0.25) 71(-6.625,-0.25) 72(-6.625,-0.75) 73(-6.625,-1.25) 74(-6.625,-1.75) 75(-6.625,-2.25) 76(-6.625,-2.75) 77(-6.625,-3.25) 78(-6.625,-3.75) 79(-6.625,-4.25) 80(-6.625,-4.75)
SC70-5L_0P65_2X1P25_B_A1
  rect 0.406x0.889 smd: 1(-0.65,-1.1) 2(0,-1.1) 3(0.65,-1.1) 4(0.65,1.1) 5(-0.65,1.1)
SOIC8_1P27_4X5
  rect 1.524x0.762 smd: 1(-2.725,1.905) 2(-2.725,0.635) 3(-2.725,-0.635) 4(-2.725,-1.905) 5(2.725,-1.905) 6(2.725,-0.635) 7(2.725,0.635) 8(2.725,1.905)
SOIC16_1P27_3P9X9P9_A1
  rect 1.549x0.61 smd: 1(-2.7,4.445) 2(-2.7,3.175) 3(-2.7,1.905) 4(-2.7,0.635) 5(-2.7,-0.635) 6(-2.7,-1.905) 7(-2.7,-3.175) 8(-2.7,-4.445) 9(2.7,-4.445) 10(2.7,-3.175) 11(2.7,-1.905) 12(2.7,-0.635) 13(2.7,0.635) 14(2.7,1.905) 15(2.7,3.175) 16(2.7,4.445)
SON6_0P5_1X1P45_A1
  rect 0.457x0.305 smd: 1(-0.275,0.5)
  rect 0.406x0.305 smd: 2(-0.3,0) 3(-0.3,-0.5) 4(0.3,-0.5) 5(0.3,0) 6(0.3,0.5)
SOT23-3L_1P9_2P9X1P3
  rect 0.813x0.914 smd: 1(-0.95,-1) 2(0.95,-1) 3(0,1)
SOT23-3L_1P9_3P12X1P5
  rect 1.016x1.397 smd: 1(-0.95,-1.1) 2(0.95,-1.1) 3(0,1.1)
SSOP16_0P635_5X4
  rect 1.803x0.356 smd: 1(-2.6,2.223) 2(-2.6,1.587) 3(-2.6,0.953) 4(-2.6,0.318) 5(-2.6,-0.318) 6(-2.6,-0.953) 7(-2.6,-1.587) 8(-2.6,-2.223) 9(2.6,-2.223) 10(2.6,-1.587) 11(2.6,-0.953) 12(2.6,-0.318) 13(2.6,0.318) 14(2.6,0.953) 15(2.6,1.587) 16(2.6,2.223)
SW3_1P7_3X2P5_SM_RA_A1
  round 0.254 hole 0.762 unplated: (0,0)
  rect 0.787x1.702 smd: 1(1.7,0) 2(-1.7,0)
  rect 0.787x1.092 smd: 3(0,-1.65)
SW3_2_8P6X4P3_TH_ST
  rect 1.651x1.651 hole 0.889: 1(0,0)
  round 1.651 hole 0.889: 2(2,0) 3(4,0)
  oval 1.956x2.718 hole 1.575: S1(-2.1,0) S2(6.1,0)
SW4_1P27_3P67X6P2
  rect 0.762x1.27 smd: 1(-0.635,-3.81) 2(0.635,-3.81) 3(0.635,3.81) 4(-0.635,3.81)
SW04_1P27_6P21X6P2
  rect 0.762x1.27 smd: 1(-1.905,-3.81) 2(-0.635,-3.81) 3(0.635,-3.81) 4(1.905,-3.81) 5(1.905,3.81) 6(0.635,3.81) 7(-0.635,3.81) 8(-1.905,3.81)
TCAP_CASED
  rect 2.616x2.692 smd: 1(-3.2,0) 2(3.2,0)
TCAP_CASEE
  rect 2.616x2.692 smd: 1(-3.2,0) 2(3.2,0)
TP35_SMD
  round 0.889 smd: 1(0,0)
TP40_SMD
  round 1.016 smd: 1(0,0)
TP40_SMD_A1
  round 1.016 smd: 1(0,0)
TP_3P8X2P03_SMD_A1
  rect 3.81x2.032 smd: 1(0,0)
TSSOP16_0P65_4P4X5_F_A1
  rect 1.499x0.457 smd: 1(-2.9,2.275) 2(-2.9,1.625) 3(-2.9,0.975) 4(-2.9,0.325) 5(-2.9,-0.325) 6(-2.9,-0.975) 7(-2.9,-1.625) 8(-2.9,-2.275) 9(2.9,-2.275) 10(2.9,-1.625) 11(2.9,-0.975) 12(2.9,-0.325) 13(2.9,0.325) 14(2.9,0.975) 15(2.9,1.625) 16(2.9,2.275)
UDFN8_0P5_3X2_EP_A_A1
  rect 0.61x0.305 smd: 1(-1.45,0.75) 2(-1.45,0.25) 3(-1.45,-0.25) 4(-1.45,-0.75) 5(1.45,-0.75) 6(1.45,-0.25) 7(1.45,0.25) 8(1.45,0.75)
  rect 1.295x1.499 smd: 9(0,0)
UDFN-6L_0P65_2X2_EP
  rect 0.406x0.432 smd: 1(-0.65,-0.938) 2(0,-0.938) 3(0.65,-0.938) 4(0.65,0.938) 5(0,0.938) 6(-0.65,0.938)
  rect 0.965x1.143 smd: 7(-0.325,0)
  rect 0.305x0.762 smd: 8(0.65,0)
VQFN48_0P4_6X6_EP_A1
  rect 0.864x0.203 smd: 1(-2.975,2.2) 2(-2.975,1.8) 3(-2.975,1.4) 4(-2.975,1) 5(-2.975,0.6) 6(-2.975,0.2) 7(-2.975,-0.2) 8(-2.975,-0.6) 9(-2.975,-1) 10(-2.975,-1.4) 11(-2.975,-1.8) 12(-2.975,-2.2) 25(2.975,-2.2) 26(2.975,-1.8) 27(2.975,-1.4) 28(2.975,-1) 29(2.975,-0.6) 30(2.975,-0.2) 31(2.975,0.2) 32(2.975,0.6) 33(2.975,1) 34(2.975,1.4) 35(2.975,1.8) 36(2.975,2.2)
  rect 0.203x0.864 smd: 13(-2.2,-2.975) 14(-1.8,-2.975) 15(-1.4,-2.975) 16(-1,-2.975) 17(-0.6,-2.975) 18(-0.2,-2.975) 19(0.2,-2.975) 20(0.6,-2.975) 21(1,-2.975) 22(1.4,-2.975) 23(1.8,-2.975) 24(2.2,-2.975) 37(2.2,2.975) 38(1.8,2.975) 39(1.4,2.975) 40(1,2.975) 41(0.6,2.975) 42(0.2,2.975) 43(-0.2,2.975) 44(-0.6,2.975) 45(-1,2.975) 46(-1.4,2.975) 47(-1.8,2.975) 48(-2.2,2.975)
  rect 4.394x4.394 smd: 49(0,0)
WLCSP6_0P5_0P96X1P46_A1
  round 0.254 smd: A1(-0.25,0.5) A2(0.25,0.5) B1(-0.25,0) B2(0.25,0) C1(-0.25,-0.5) C2(0.25,-0.5)
WPDFN8_1P27_6X5_EP_A1
  rect 0.864x0.406 smd: 1(-2.825,1.905) 2(-2.825,0.635) 3(-2.825,-0.635) 4(-2.825,-1.905) 5(2.825,-1.905) 6(2.825,-0.635) 7(2.825,0.635) 8(2.825,1.905)
  rect 2.997x2.997 smd: 9(0,0)
XTAL2_2P5_3P2X1P5
  rect 1.016x1.803 smd: 1(-1.25,0) 2(1.25,0)
XTAL4_1P6_3P2X2P5_A_A1
  rect 1.397x1.168 smd: 1(-1.1,-0.8) 2(1.1,-0.8) 3(1.1,0.8) 4(-1.1,0.8)
XTAL4_1P55_3P2X2P5
  rect 1.016x0.914 smd: 1(-1.075,-0.775) 2(1.075,-0.775) 3(1.075,0.775) 4(-1.075,0.775)

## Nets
3V3_OUT: R168.2 U20.10
5VIN: C1.1 C2.1 F1.2 Q1.4 Q1.8(SOURCE2) Q2.2(EMITTER) R1.2 R3.2 R6.1
GND: BH1.2 C1.2 C3.2(CATHODE) C4.2 C5.2 C6.2 C7.2 C8.2 C9.2 C10.2 C11.2 C12.2 C13.2 C14.2 C15.2 C16.2 C17.2 C18.2 C19.2 C20.2 C21.2 C22.2 C23.2 C24.2 C26.2 C27.2 C28.2 C29.2 C30.2 C31.2 C32.2 C33.2 C34.2 C35.2 C36.2 C37.2 C38.2 C39.2 C40.2 C41.2 C42.2 C43.2 C44.2 C45.2 C46.2 C47.2 C48.2 C49.2 C50.2 C51.2 C52.2 C53.2 C54.2 C55.2 C56.2 C57.2 C58.2 C59.2 C60.2 C61.2 C62.2 C63.2 C64.2 C65.2 C66.2 C67.2 C68.2 C69.2 C70.2 C71.2 C72.2 C73.2 C74.2 C75.2 C76.2 C77.2 C78.2 C79.2 C80.2 C81.2 C82.2 C83.2 C84.2 C85.2 C86.2 C87.2 C88.2 C89.2 C90.2 C91.2 C92.2 C93.2 C94.2 C95.2 C96.2 C97.2 C98.2 C99.2 C100.2 C101.2 C102.2 C103.2 C104.2 C105.2 C106.2 C107.2 C108.2 C109.2 C110.2 C111.2 C112.2 C113.2 C114.2 C115.2 C116.2 C117.2 C118.2 C119.2 C120.2 C121.2 C122.1 C123.1 C124.1 C125.1 C126.2 C127.2 C128.2 C129.2 C130.2 C131.2 C132.2 C133.2 C134.2 C135.2 C136.2 C137.2 C138.2 C139.2 C140.2 C141.2 C142.2 C143.2 C149.2 C150.2 C151.2 C152.2 C153.2 C154.2 C155.2 C156.2 C157.2 C158.2 C159.2 C160.2 C161.2 C162.2 C163.2 C164.2 C165.2 C166.2 C167.1 C168.2 C169.1 C170.2 C171.2 C172.2 C173.2 C174.2 C175.2 C176.2 C177.2 C180.2 C181.2 C182.2 C183.2 C184.2 C185.2 C186.2 C187.2 C188.2 C189.1 C190.2 C191.1 C192.1 C193.1 C194.1 C195.2 C196.2 C197.2 C198.2 C199.2 C200.2 C201.2 C204.2 C205.2 C572.2 C573.2 C574.2 C575.2 C576.2 C577.2 C583.2 C584.2 C585.2 C586.2 C587.2 C588.2 C589.2 C590.2(CATHODE) C591.1 C592.1 C593.1 C594.1 C596.2 C597.2 C598.2 C599.2 C600.2 C601.1 C602.1 C603.1 C604.1 C605.1 C606.1 C607.2 D1.2 D5.1(K) DA1.4(RK) DA2.4(RK) DA3.4(RK) DA4.4(RK) DA5.4(RK) DA8.4(OK) FB5.2 FB15.1 FB16.1 H1.6 H4.11 H4.13 H4.15 H4.17 H4.19 H5.4 H5.6 H5.8 H5.10 H5.12 H5.14 H5.16 H5.18 H5.20 J1.2 J1.S1 J1.S2 J2.6(VSS) J3.S1 J3.S2 J3.S3 J3.S4 J4.4 J4.8 J4.S1 J4.S2 J4.S3 J4.S4 J5.4 J5.8 J5.S1 J5.S2 J5.S3 J5.S4 J6.4 J6.S1 J6.S2 J6.S3 J6.S4 J7.S1 J7.S2 J7.S3 J7.S4 J9.2 J9.4 J9.5 J9.6 J9.7 J9.8 J9.40 J9.M1 J9.M2 MH1.1 MH2.1 MH3.1 MH4.1 MH5.1 MH6.1 MH7.1 MH8.1 P1.1 P2.1 P3.1 P4.1 P5.1 P6.1 P7.1 P8.1 P9.1 P10.1 P11.1 P12.1 P13.1 P14.1 P15.1 Q3.2(SOURCE) Q17.2(EMITTER) Q41.2(EMITTER) R9.1 R14.2 R15.1 R16.2 R17.1 R19.2 R21.2 R24.1 R37.2 R58.2 R60.2 R62.2 R63.1 R64.1 R65.2 R68.1 R103.1 R121.1 R127.1 R129.2 R133.2 R135.1 R144.2 R145.2 R146.2 R147.2 R149.2 R152.2 R154.2 R166.2 R173.2 R174.1 R178.2 R179.1 R194.2 R197.2 R236.1 R238.1 R239.1 R240.1 R241.1 R242.1 R243.1 R244.1 R245.1 R246.1 R247.1 R248.1 R249.1 R250.1 R251.1 R252.1 R253.1 R254.1 R255.1 R256.1 R257.1 R258.1 R259.1 R260.1 R569.1 R572.2 R574.2 R577.1 R579.2 R770.1 R772.2 R773.1 R779.1 R805.2 R806.2 R808.2 R815.1 R821.1 R832.1 R836.2 R843.1 R848.1 R851.1 R852.1 SW1.2 SW1.3 SW1.S1 SW1.S2 SW2.1 SW2.3 SW3.1 SW3.3 SW4.1 SW4.3 SW5.1 SW5.3 SW8.1 SW8.3 TP30.1 TP31.1 TP32.1 TP41.1 TP42.1 TP43.1 TP51.1 TP55.1 TP56.1 TP57.1 U1.49 U2.3 U3.C1 U4.C1 U5.C1 U6.A1 U6.A17 U6.C3 U6.C7 U6.C11 U6.C15 U6.E8 U6.E11 U6.F6 U6.F7 U6.F8 U6.F9 U6.F10 U6.F11 U6.F12 U6.G3 U6.G5 U6.G7 U6.G12 U6.G15 U6.H7 U6.H12 U6.J5 U6.J7 U6.J12 U6.K7 U6.K12 U6.L3 U6.L7 U6.L12 U6.M7 U6.M8 U6.M9 U6.M10 U6.M11 U6.M12 U6.N3 U6.N5 U6.N7 U6.R3 U6.R5 U6.R7 U6.R11 U6.R16 U6.R17 U6.T14 U6.U1 U6.U14 U6.U17 U7.A9 U7.B1 U7.B3 U7.B9 U7.D1 U7.D8 U7.E1 U7.E2 U7.E8 U7.F9 U7.G1 U7.G8 U7.G9 U7.J2 U7.J8 U7.M1 U7.M9 U7.P1 U7.P9 U7.T1 U7.T9 U8.A6 U8.C4 U8.E7 U8.G5 U8.H10 U8.J5 U8.K8 U8.N2 U8.N5 U8.P4 U8.P6 U9.4 U9.9 U10.6 U10.10 U10.22 U10.25 U10.29 U10.33 U10.37 U10.40 U10.52 U10.55 U10.64 U10.77 U11.3 U11.8 U12.3 U12.8 U13.1 U13.2 U13.3 U13.4 U13.7(WP) U13.9 U14.19 U14.65 U15.3 U15.8 U16.3 U16.8 U17.3 U17.8 U18.1 U18.5 U19.6 U20.5 U20.13 U21.C2 U22.3 U22.5 U22.17 U23.3 U23.17 U24.6 U26.2 U26.6 U27.3 X1.2 X1.4 X3.2 X3.4(GND2) Y1.2
GND_DEBUGUSB_CONN: C177.1 J8.S1 J8.S2 J8.S3 J8.S4 J8.S5 J8.S6 R178.1
VBUS1_FL: C601.2 FB10.2 J4.1 P9.2
VBUS2_FL: C602.2 FB11.2 J4.5(VBUS2) P10.2
VBUS3_FL: C603.2 FB12.2 J5.1 P11.2
VBUS4_FL: C604.2 FB13.2 J5.5(VBUS2) P12.2
VBUS5_FL: C605.2 FB14.2 J6.1(VBUS) P13.2
VBUS_DEBUG_USB_5V: FB4.1 J8.1(VBUS)
VBUS_DET: R175.2 R179.2 U20.15
VBUS_DET_HUB: R140.2 U14.44
VCCI_EMMC: C110.1 C111.1 U8.C2
VDD_1V0: C30.1 L5.2 TP37.1 U1.21
VDD_1V8: C39.1 C90.1 C106.1 C107.1 C108.1 C109.1 C112.1 C113.1 C587.1 C588.1 FB8.1 H4.7 H4.9 R69.1 R94.1 R95.1 R96.1 R97.1 R98.1 R99.1 R100.1 R101.1 R102.1 R104.2 R183.2 R858.1 TP8.1 U4.C2 U6.E7 U8.C6 U8.M4 U8.N4 U8.P3 U8.P5 U9.8 U23.11
VDD_1V8_SNS: C19.1 C20.1 R183.1 TP47.1 U1.15 U23.12
VDD_ARM_CAP: C46.1 C47.1 C48.1 TP49.1 U6.G9 U6.G10 U6.G11 U6.H11
VDD_CENT_TAP_A1: C122.2 FB17.2 J3.7
VDD_CENT_TAP_A2: C123.2 FB18.2 J3.12
VDD_CENT_TAP_B1: C124.2 FB19.2 J3.14
VDD_CENT_TAP_B2: C125.2 FB20.2 J3.22
VDD_COINCELL_IN: BH1.1 BH1.3(POS2) C37.1 R11.2 R32.1
VDD_DCDC6: C31.1 L6.2 R13.2 R802.2
VDD_DCJACK_5VIN: F1.1 J1.1
VDD_ETH_ANA_3V3: C116.1 FB1.2 U10.30
VDD_EXT_LS_5V0: C157.1 C158.1 C165.1 R189.1 R800.1 R801.1 R865.1 TP13.1 U18.2 U19.7 U23.1
VDD_EXT_LS_5V0_SNS: C43.1 R189.2 U5.A1 U5.B1(VOUT2) U23.2
VDD_HIGH_CAP: C57.1 C58.1 C72.1 TP52.1 U6.N6 U6.R14 U6.R15
VDD_HIGH_IN_3V3: C27.1 C28.1 C35.1 C36.1 C40.1 C55.1 C56.1 D6.2 R28.2 R34.2 R35.2 R188.1 TP12.1 U1.5 U1.31 U1.39 U3.A2 U3.B2 U4.A2 U6.N13 U22.1
VDD_HIGH_IN_3V3_SNS: C10.1 C11.1 L3.2 R188.2 TP46.1 U22.2
VDD_HUB_LED: D9.1(K) DA1.1 DA2.1 DA3.1 DA4.1 DA5.1
VDD_IN_BU: C600.1 R12.1 U1.27
VDD_LCD: C182.1 C185.1 J9.34 Q4.3 R190.2
VDD_LCD_BCKLIGHT: C197.1 C199.1 J9.3 Q6.3 R261.2
VDD_LCD_SW_IN: C184.1 FB7.2 FB9.2 Q4.2(SOURCE) R190.1 R192.1
VDD_LDO1: C21.1 C22.1 R780.2 U1.4
VDD_LDO_2V8: FB7.1 R780.1 TP38.1
VDD_NVCC_3V3: C26.1 C29.1 C91.1 C96.1 C99.1 C100.1 C101.1 C102.1 C573.1 D15.1 DA6.1 DA6.2 R16.1 R25.2 R70.1 R86.1 R137.1 R138.1 R164.1 R181.1 R182.1 R204.1 R208.1 R578.1 R580.1 R581.1 R814.1 R839.1 R840.1 R866.1 R867.1 R868.1 R869.1 R870.1 R871.1 R874.1 TP39.1 U1.30 U2.1 U6.F4 U6.F13 U6.H13 U6.J13(NVCC_GPIO) U6.L13 U6.M13 U26.4(VCC) U27.5
VDD_NVCC_SD1: C42.1 C92.1 R72.1 R73.1 R74.1 R75.1 R76.1 U4.B2(VOUT) U6.C4
VDD_OTG1_VBUS: C168.1 C169.2 FB3.1 U19.5(OUTB)
VDD_PERI_3V3: C38.1 C103.1 C104.1 C105.1 C114.1 C115.1 C117.1 C118.1 C119.1 C120.1 C121.1 C128.1 C170.1 C171.1 C172.1 C173.1 C180.1 C181.1 C188.1 C190.1 C198.1 C585.1 C586.1 C597.1 C607.1 D9.2 D29.2 FB1.1 FB6.1 FB9.1 FB17.1 FB18.1 FB19.1 FB20.1 H4.5 J2.4 L7.1 Q6.2(SOURCE) R77.1 R109.1 R110.2 R113.2 R114.2 R115.2 R116.1 R120.2 R124.1 R128.2 R130.2 R131.1 R134.1 R167.2 R168.1 R176.1 R177.1 R180.2 R185.2 R261.1 R262.1 R264.1 R265.2 R267.2 R387.2 R571.1 R783.2 R784.2 R785.2 R798.2 R799.2 R810.2 R811.2 R812.2 R813.2 R844.1 R845.2 R846.1 R847.2 R854.2 R855.2 R857.2 R863.1 R864.1 U3.A1 U3.B1(VOUT2) U8.E6 U8.F5 U8.J10 U8.K9 U10.11 U10.51 U10.65 U10.78 U13.8 U20.3(VCCIO) U20.12 U22.4 U22.16 U23.4 U23.16 U24.1 U24.7 U24.10 Y1.4(VDD)
VDD_PERI_FIL_3V3: C131.1 C133.1 C137.1 C138.1 C139.1 C140.1 C141.1 C142.1 C143.1 C589.1 L7.2 R140.1 R141.1 R142.1 R143.1 R161.1 R162.1 R163.1 R165.1 R816.2 R817.2 R818.2 R819.2 R820.2 U14.5 U14.10 U14.24 U14.46 U14.52 U14.57 U14.64
VDD_PMIC_LS_5V0: C94.1 C95.1 C159.1 C160.1 R36.1 R187.1 R800.2 R801.2 R865.2 TP11.1 U6.T12 U6.U12 U18.6 U23.14
VDD_PMIC_LS_5V0_SNS: C23.1 C24.1 R187.2 U1.7 U1.33 U23.15
VDD_SNVS_CAP: C62.1 TP54.1 U6.N12
VDD_SNVS_IN: C61.1 D6.1(K) R18.2 R23.1 R26.1 R27.1 R32.2 R575.1 R576.1 R763.2 R802.1 TP36.1 U2.5 U6.P12
VDD_SOC_ARM_IN: C44.1 C45.1 C49.1 C50.1 R184.2 TP9.1 U1.47 U6.H9 U6.H10 U6.J9 U6.J10 U6.K9 U6.K10 U22.11
VDD_SOC_ARM_IN_SNS: C7.1 C8.1 L1.2 R184.1 TP44.1 U22.12
VDD_SOC_CAP: C51.1 C52.1 C53.1 C54.1 TP50.1 U6.G8 U6.H8 U6.J8 U6.J11 U6.K8 U6.K11 U6.L8 U6.L9 U6.L10 U6.L11
VDD_USB_VBUS1: C149.1 C150.1 FB10.1 U18.15
VDD_USB_VBUS2: C151.1 C152.1 FB11.1 U18.14
VDD_USB_VBUS3: C153.1 C154.1 FB12.1 U18.11
VDD_USB_VBUS4: C155.1 C156.1 FB13.1 U18.10(OUT4)
VDD_USB_VBUS5: C166.1 C167.2 FB14.1 U19.8
VIN_PMIC_5V0: C3.1 C4.1 C5.1 C6.1 C12.1 C13.1 C14.1 C15.1 C16.1 C17.1 C41.1 C583.1 C584.1 C590.1 C596.1 DA8.1 H4.1 H4.3 P1.2 Q1.1 Q1.2 Q1.5 Q1.6 Q1.7 R7.2 R10.2 R12.2 R20.2 R22.2 R781.1 TP1.1 U1.1 U1.6 U1.12 U1.32 U1.36 U1.37 U1.43 U5.A2 U5.B2
BASE_CC#: Q17.1 R766.2
BOOST0: R149.1 U14.50
BOOST1: R152.1 U14.48
BOOT_MODE0: SW7.2 U6.T10
BOOT_MODE1: SW7.1 U6.U10
BUSY: R199.2 U24.13
CCM_PMIC_STBY_REQ: R765.1 U6.U9
CLOCK_50MHZ: R132.1 Y1.3
CMD: R830.2 U8.M5
COLL_CC#: DA8.2 Q17.3 R781.2 R782.1
CRS_DV_A: R119.2 R572.1 U10.1
CRS_DV_B: R126.2 R574.1 U10.61
CS#: R201.2 U24.15
CSENS2_A0: R185.1 U23.5
DAT0: R822.2 U8.A3
DAT1: R823.2 U8.A4
DAT2: R824.2 U8.A5
DAT3: R825.2 U8.B2
DAT4: R826.2 U8.B3
DAT5: R827.2 U8.B4
DAT6: R828.2 U8.B5
DAT7: R829.2 U8.B6
DC34_SEL: R21.1 U1.17
DC_SW: R5.1 SW1.1
DC_SW_CTL: C2.2 D2.1(K) Q1.3 R3.1 R5.2
DCDC1_L1: L1.1 U1.48
DCDC2_L2: L2.1 U1.42
DCDC3_L3: L3.1 U1.38
DCDC4_L4A: L4.1 U1.13
DCDC4_L4B: L4.2 U1.14
DCDC5_L5: L5.1 U1.20
DCDC6_L6: L6.1 U1.23
DDR_ZQPAD: R63.2 U7.L8(ZQ)
DEBUG_5V0: C174.1 FB4.2 R175.1
DEBUG_DN: R172.1 U21.B1(OUT2)
DEBUG_DP: R171.1 U21.A1
DEBUG_RESET#: R180.1 R831.2 U20.11
DEBUG_RXD: R170.1 U20.4
DEBUG_TXD: R169.1 U20.1
DEBUG_UART_RESET#: R831.1 U6.E5
DEBUG_USB_DN: J8.2 U21.B2
DEBUG_USB_DP: J8.3 U21.A2
DRAM_ADDR0: U6.L5 U7.N3
DRAM_ADDR1: U6.H2 U7.P7
DRAM_ADDR2: U6.K1 U7.P3
DRAM_ADDR3: U6.M2 U7.N2
DRAM_ADDR4: U6.K4 U7.P8
DRAM_ADDR5: U6.L1 U7.P2
DRAM_ADDR6: U6.G2 U7.R8
DRAM_ADDR7: U6.H4 U7.R2
DRAM_ADDR8: U6.J4 U7.T8
DRAM_ADDR9: U6.L2 U7.R3
DRAM_ADDR10: U6.M4 U7.L7
DRAM_ADDR11: U6.K3 U7.R7
DRAM_ADDR12: U6.L4 U7.N7
DRAM_ADDR13: U6.H3 U7.T3
DRAM_ADDR14: U6.G1 U7.T7
DRAM_ADDR15: U6.K5 U7.M7
DRAM_CAS#: U6.J2 U7.K3
DRAM_CS0#: U6.N2 U7.L2
DRAM_CS1#: U6.H5 U7.L1
DRAM_DATA0: U6.T4 U7.E3
DRAM_DATA1: U6.U6 U7.F7
DRAM_DATA2: U6.T6 U7.F2
DRAM_DATA3: U6.U7 U7.F8
DRAM_DATA4: U6.U8 U7.H3
DRAM_DATA5: U6.T8 U7.H8
DRAM_DATA6: U6.T5 U7.G2
DRAM_DATA7: U6.U4 U7.H7
DRAM_DATA8: U6.U2 U7.D7
DRAM_DATA9: U6.U3 U7.C3
DRAM_DATA10: U6.U5 U7.C8
DRAM_DATA11: U6.R4 U7.C2
DRAM_DATA12: U6.P5 U7.A7
DRAM_DATA13: U6.P3 U7.A2
DRAM_DATA14: U6.R2 U7.B8
DRAM_DATA15: U6.R1 U7.A3
DRAM_DQM0: U6.T7 U7.E7
DRAM_DQM1: U6.T3 U7.D3
DRAM_ODT0: U6.N1 U7.K1
DRAM_ODT1: U6.F1 U7.J1
DRAM_RAS#: U6.M5 U7.J3
DRAM_RESET#: R64.2 U6.G4 U7.T2
DRAM_SDBA0: U6.M1 U7.M2
DRAM_SDBA1: U6.H1 U7.N8
DRAM_SDBA2: U6.K2 U7.M3
DRAM_SDCKE0: R60.1 U6.M3 U7.K9
DRAM_SDCKE1: R58.1 U6.J3 U7.J9
DRAM_SDCLK0_N: R67.1 U6.P2 U7.K7
DRAM_SDCLK0_P: R67.2 U6.P1 U7.J7
DRAM_SDQS0_N: U6.P7 U7.G3
DRAM_SDQS0_P: U6.P6 U7.F3
DRAM_SDQS1_N: U6.T2 U7.B7
DRAM_SDQS1_P: U6.T1 U7.C7
DRAM_SDWE#: U6.J1 U7.L3
DRAM_VREF: C63.1 C64.1 C73.1 C88.1 R66.1 R68.2 U6.P4 U7.H1 U7.M8
DRAM_ZQPAD: R65.1 U6.N4
ED_EN_A: R798.1 U10.9
ED_EN_B: R799.1 U10.53
EEPR_SCL: R136.2 U13.6
EEPR_SDA: R139.2 U13.5
ENET1_TXD0: R78.2 U6.E15
ENET1_TXD1: R79.2 U6.E14
ENET1_TXEN: R80.2 U6.F15
ENET2_TXD0: R83.2 U6.A15
ENET2_TXD1: R84.2 U6.A16
ENET2_TXEN: R85.2 U6.B15
ENET_INT_A: R861.1 R863.2 U10.18
ENET_INT_B: R862.1 R864.2 U10.44
ENET_REF_CLK: R773.2 R779.2 U6.D17 U6.F14 U10.68
ENETPHY_RESET#: R127.2 TP48.1 U6.L17 U10.71
EXT_EN: R571.2 U10.56
FB_DCDC6: R13.1 R14.1 U1.22
FT230_CTS#: R174.2 U20.6
FT230_RTS#: TP7.1 U20.2
GANG_EN: R154.1 U14.34
GATE_PMOS: D12.2 Q4.1 Q5.1 Q6.1 R192.2 R193.2 R262.2
GPANIO: U6.R13
GPIO1_IO22: H4.2 R841.1
GPIO1_IO24: R861.2 U6.H17
GPIO1_IO25: R862.2 U6.H16
GPIO3_IO03: H4.20 U6.C9
GPIO5_IO02: H4.4 R834.2
GPIO5_IO03: H4.6 R835.2
GPIO5_IO04: H4.8 R866.2 U6.P9
GPIO5_IO05: H4.10 R867.2 U6.N8
GPIO5_IO06: H4.12 R868.2 U6.N11
GPIO5_IO07: H4.14 R869.2 U6.N10
GPIO5_IO08: H4.16 R870.2 U6.N9
GPIO5_IO09: H4.18 R871.2 U6.R6
HUB_CFG_SEL1: R142.2 R146.1 U14.42
HUB_CFG_SEL2: R143.2 R147.1 U14.13
HUB_LEDA1#: DA1.2 DA1.3 R150.2
HUB_LEDA2#: DA2.2 DA2.3 R151.2
HUB_LEDA3#: DA3.2 DA3.3 R153.2
HUB_LEDA4#: DA4.2 DA4.3 R157.2
HUB_LEDA5#: DA5.2 DA5.3 R158.2
HUB_OCS1#: C161.1 R155.2 U14.28
HUB_OCS2#: C162.1 R156.2 U14.27
HUB_OCS3#: C163.1 R159.2 U14.22
HUB_OCS4#: C164.1 R160.2 U14.21
HUB_OCS5#: R820.1 U14.35 U19.2
HUB_PWR_EN1: U14.29 U18.3
HUB_PWR_EN2: U14.26 U18.4
HUB_PWR_EN3: U14.23 U18.7
HUB_PWR_EN4: U14.20 U18.8
HUB_PWR_EN5: U14.30 U19.1
HUB_RESET#: R144.1 TP60.1 U6.N17 U14.43
HUB_VDDA18PLL: C132.1 C134.1 U14.62
HUB_VDDDIG18: C135.1 C136.1 U14.25
I2C2_CURSENSE_SCL: R181.2 U6.F17 U22.6 U23.6
I2C2_CURSENSE_SDA: R182.2 U6.G13 U22.7 U23.7
I2C4_HUB_EEPR_SCL: R89.1 R136.1 R137.2 R145.1 TP59.1 U14.41
I2C4_HUB_EEPR_SDA: R90.1 R138.2 R139.1 TP58.1 U14.40
I2C4_SCL: R89.2 U6.J17
I2C4_SDATA: R90.2 U6.J16
I.MX_ONOFF: C598.1 SW3.2 U6.R8
INT_LDO: C34.1 U1.35
IOVDD_LCD: C183.1 C187.1 J9.33 Q5.3 R191.2 R195.1 R807.1
IOVDD_LCD_SW_IN: C186.1 FB6.2 FB8.2 Q5.2(SOURCE) R191.1 R193.1
JTAG_DACK: H5.19 R848.2
JTAG_DE: H5.17 R265.1
JTAG_MOD: R387.1 R569.2 U6.P15
JTAG_PWR: C572.1 H5.2 R264.2
JTAG_RTCK: H5.11 R851.2
JTAG_SRST#: D26.1(K) H5.15 R266.1 R856.2
JTAG_TCK: H5.9 R852.2 U6.M14
JTAG_TDI: H5.5 R854.1 U6.N16
JTAG_TDO: H5.13 U6.N15
JTAG_TMS: H5.7 R267.1 U6.P14
JTAG_TRST#: H5.3 R855.1 R856.1 U6.N14
JTAG_VREF: H5.1 R857.1
LCD_CS#: J9.31 R194.1
LCD_DATA0: J9.27 R236.2 SW6.1 U6.B9
LCD_DATA1: J9.26 R231.2 R238.2 U6.A9
LCD_DATA2: J9.25 R230.2 R239.2 U6.E10
LCD_DATA3: J9.24 R229.2 R240.2 U6.D10
LCD_DATA4: J9.23 R228.1 R241.2 U6.C10
LCD_DATA5: J9.22 R242.2 SW6.2 U6.B10
LCD_DATA6: J9.21 R243.2 SW6.3 U6.A10
LCD_DATA7: J9.20 R244.2 SW6.4 U6.D11
LCD_DATA8: J9.19 R224.2 R245.2 U6.B11
LCD_DATA9: J9.18 R223.2 R246.2 U6.A11
LCD_DATA10: J9.17 R222.2 R247.2 U6.E12
LCD_DATA11: J9.16 R221.2 R248.2 U6.D12
LCD_DATA12: J9.15 R220.2 R249.2 U6.C12
LCD_DATA13: J9.14 R219.2 R250.2 U6.B12
LCD_DATA14: J9.13 R218.2 R251.2 U6.A12
LCD_DATA15: J9.12 R217.2 R252.2 U6.D13
LCD_DATA16: R216.2 R253.2 U6.C13
LCD_DATA17: R215.2 R254.2 U6.B13
LCD_DATA18: R214.2 R255.2 U6.A13
LCD_DATA19: R213.2 R256.2 U6.D14
LCD_DATA20: R212.2 R257.2 U6.C14
LCD_DATA21: R211.2 R258.2 U6.B14
LCD_DATA22: R210.2 R259.2 U6.A14
LCD_DATA23: R209.2 R260.2 U6.B16
LCD_DATA/COMND: J9.30 U6.D9
LCD_IM0: J9.10 R195.2 R197.1
LCD_PWR_EN: D12.1(K) U6.H14
LCD_RD_E#: J9.28 U6.B8
LCD_RESET#: R196.1 R807.2 R808.1 U6.E9
LCD_WR_E#: J9.29 U6.A8
LED_ACT/COL_A: D7.1(K) R110.1 U10.21
LED_ACT/COL_B: D8.1(K) R128.1 U10.41
LED_LINK_A: J3.31 R844.2 U10.19
LED_LINK_B: J3.27 R846.2 U10.43
LED_SPEED_A: J3.34 R845.1 U10.20
LED_SPEED_B: J3.30 R847.1 U10.42
LOCAL_PWR: R141.2 U14.45
MII_MODE_A: R783.1 U10.80
MII_MODE_B: R784.1 U10.62
NVCC_DRAM_1V35: C65.1 C66.1 C67.1 C68.1 C69.1 C70.1 C71.1 C74.1 C75.1 C76.1 C77.1 C78.1 C79.1 C80.1 C81.1 C82.1 C83.1 C84.1 C85.1 C86.1 C87.1 R66.2 R186.2 TP10.1 U1.41 U6.G6 U6.H6 U6.J6 U6.K6 U6.L6 U6.M6 U7.A1 U7.A8 U7.B2 U7.C1 U7.C9 U7.D2 U7.D9 U7.E9 U7.F1 U7.G7 U7.H2 U7.H9 U7.K2 U7.K8 U7.N1 U7.N9 U7.R1 U7.R9 U22.14
NVCC_DRAM_1V35_SNS: C9.1 C18.1 L2.2 R186.1 TP45.1 U22.15
NVCC_LCD: C89.1 R69.2 R70.2 R209.1 R210.1 R211.1 R212.1 R213.1 R214.1 R215.1 R216.1 R217.1 R218.1 R219.1 R220.1 R221.1 R222.1 R223.1 R224.1 R225.2 R226.2 R227.2 R228.2 R229.1 R230.1 R231.1 R232.2 U6.E13
NVCC_PLL: C59.1 C60.1 TP53.1 U6.P13
ON_LS4: R36.2 R806.1 U5.C2
ON_LS5: R31.1 R805.1 U3.C2
OTG_DM: FL6.2 J7.2 U17.1 U17.10(NC4)
OTG_DP: FL6.3 J7.3 U17.2 U17.9
OTG_PWR: C606.2 FB3.2 J7.1(VBUS) U17.5 U17.6
OVRPRTC: Q3.1 R8.1 R9.2
OVRPRTC_LED: D4.1(K) Q3.3
OVRPRTC_LED_PWR: D4.2 R6.2
PB_RESET: D27.1(K) SW8.2
PFBIN: C126.1 C127.1 C574.1 C575.1 C576.1 C577.1 U10.7 U10.28 U10.31 U10.34 U10.54
PFO#: R27.2 R860.1 U6.R9
PGOOD: R769.2 U1.8
PGOOD_BU: R768.2 U1.19
PHY_MDC: TP5.1 U6.L16 U10.67
PHY_MDIO: R113.1 TP6.1 U6.K17 U10.66
PHYA_CRSDV: R119.1 U6.E16
PHYA_MDI_1_N: J3.13 R791.2 U10.26 U11.2 U11.9
PHYA_MDI_1_P: J3.6 R790.1 U10.27 U11.1 U11.10(NC4)
PHYA_MDI_2_N: J3.5 R793.2 U10.23 U11.5 U11.6
PHYA_MDI_2_P: J3.11 R792.1 U10.24 U11.4 U11.7
PHYA_RXD0: R112.2 U6.F16
PHYA_RXD1: R117.2 U6.E17
PHYA_RXER: R114.1 R118.2 U6.D15
PHYA_TX_EN: R80.1 U10.13
PHYA_TXD0: R78.1 U10.14
PHYA_TXD1: R79.1 U10.15
PHYB_CRSDV: R126.1 U6.B17
PHYB_MDI_1_N: J3.21 R795.2 U10.36 U12.2 U12.9
PHYB_MDI_1_P: J3.15 R794.1 U10.35 U12.1 U12.10(NC4)
PHYB_MDI_2_N: J3.16 R797.2 U10.39 U12.5 U12.6
PHYB_MDI_2_P: J3.23 R796.1 U10.38 U12.4 U12.7
PHYB_RXD0: R122.2 U6.C17
PHYB_RXD1: R123.2 U6.C16
PHYB_RXER: R115.1 R125.2 U6.D16
PHYB_TX_EN: R85.1 U10.49
PHYB_TXD0: R83.1 U10.48
PHYB_TXD1: R84.1 U10.47
PMIC_AC_DET: R10.1 R15.2 U1.9
PMIC_CC: C32.1 R11.1 U1.25
PMIC_GPIO1: R28.1 R31.2 U1.11
PMIC_I2C1_SCL: R580.2 R875.1 U1.3 U6.G17
PMIC_I2C1_SDA: R581.2 R876.2 U1.2 U6.G16
PMIC_IN_CC#: R766.1 U1.18
PMIC_INT#: R25.1 U1.45 U6.F5
PMIC_PB: R841.2 R842.1 U6.J15
PMIC_PB_B: R20.1 R842.2 R843.2 SW2.2 U1.44
PMIC_PFI: R22.1 R24.2 U1.16
PMIC_PFO#: R859.2 R860.2 U1.10
PMIC_PGOOD: R23.2 R768.1 R769.1 TP40.1 U2.2
PMIC_PWR_EN: R18.1 R19.1 R88.2 R833.1 R859.1 TP34.1 U1.46 U26.1
PMIC_PWR_EN_R: R88.1 U6.T9
PMIC_STBY_REQ: Q41.1 R765.2
PMIC_WAKE#: R26.2 U1.40(WAKEUP#) U6.R10
POR_B: D26.2 R803.1 TP35.1 U6.P8 U27.1
PRTDIS_M6: R162.2 U14.53
PRTDIS_M7: R165.2 U14.55
PRTDIS_P6: R161.2 U14.54
PRTDIS_P7: R163.2 U14.56(USBDN7_DP/PRT_DIS_P7)
PWR_OV_BASE: Q2.1 R4.1
PWR_OV_CTL: D1.1(K) R1.1 R4.2
PWR_OVP_LED: D2.2 Q2.3 R8.2
QSPIA_DATA0: TP3.1 U6.A3 U9.5
QSPIA_DATA1: U6.C5 U9.2
QSPIA_DATA2: U6.B5 U9.3(W#/DQ2)
QSPIA_DATA3: U6.A4 U9.7
QSPIA_SCLK: R809.2 TP4.1 U9.6
QSPIA_SS0#: R104.1 U6.E6 U9.1
RBIAS: R129.1 U10.32
RBIAS_HUB: R577.2 U14.63
RES#: J9.11 R196.2
RES_LED1: DA6.4(RK) R205.1
RES_LED2: DA6.3 R206.1
RES_LED3: D15.2(K) R207.1
REV_CHANGE: R814.2 R815.2 U6.L14
REVRES_1: R834.1 R836.1 R839.2 U6.P11
REVRES_2: R772.1 R835.1 R840.2 U6.P10
RTC_XTALI: C200.1 U6.T11 X2.1
RTC_XTALO: C201.1 U6.U11 X2.2
RXD0_A: R112.1 R785.1 U10.4
RXD0_B: R122.1 U10.58
RXD1_A: R117.1 U10.5
RXD1_B: R123.1 U10.57
RXER_A: R118.1 U10.2
RXER_B: R125.1 U10.60
RXLED: D11.1(K) U20.14
SD1_CD#: J2.CD1 J2.CD2 P2.2 R77.2 R87.1
